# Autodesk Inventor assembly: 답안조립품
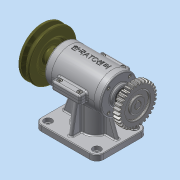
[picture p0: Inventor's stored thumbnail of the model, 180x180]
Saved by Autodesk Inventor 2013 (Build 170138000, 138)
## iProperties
Created: 2015-09
Part Number: 답안조립품
Document SubType Name: Assembly
Designer: dgall
Mass: 2246.61 g
Surface Area: 1628.2 cm^2
Volume: 528.248 cm^3
Density: 4.25295 g/cm^3
Author: dgall
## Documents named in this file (17)
- C:\Users\dgall\Desktop\350907V1040\답안조립품.iam
- C:\Users\dgall\Desktop\350907V1040\1본체.ipt
- C:\Users\dgall\Desktop\350907V1040\2본체 커버.ipt
- C:\Users\dgall\Desktop\350907V1040\3앞커버.ipt
- C:\Users\dgall\Desktop\350907V1040\4뒤커버.ipt
- C:\Users\dgall\Desktop\350907V1040\5편심축.ipt
- C:\Users\dgall\Desktop\350907V1040\6V-벨트풀리.ipt
- C:\Users\dgall\Desktop\350907V1040\7슬라이드.ipt
- C:\Users\dgall\Desktop\350907V1040\8스퍼기어.ipt
- C:\Users\dgall\Desktop\350907V1040\9베어링 6202.ipt
- C:\Users\dgall\Desktop\350907V1040\10베어링 6201.ipt
- C:\Users\dgall\Desktop\350907V1040\11오일실.ipt
- C:\Users\dgall\Desktop\350907V1040\12M4x0.5x14.ipt
- C:\Users\dgall\Desktop\350907V1040\13M3x0.5x8.ipt
- C:\Users\dgall\Desktop\350907V1040\14멈춤나사.ipt
- C:\Users\dgall\Desktop\350907V1040\15키4x4.ipt
- C:\Users\dgall\Desktop\350907V1040\16가변스프링.ipt
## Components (28 placed, 15 different names)
1. 1본체:1 — 각도:1
2. 2본체 커버:1
3. 3앞커버:1
4. 4뒤커버:1
5. 5편심축:1 — 각도:1
6. 6V-벨트풀리:1
7. 7슬라이드:1
8. 9베어링 6202:1
9. 10베어링 6201:1
10. 11오일실:1
11. 11오일실:2
12. M4x0.5x14:1
13. M4x0.5x14:2
14. M4x0.5x14:3
15. M4x0.5x14:4
16. M3x0.5x8:1
17. M3x0.5x8:2
18. M3x0.5x8:3
19. M3x0.5x8:4
20. M3x0.5x8:5
21. M3x0.5x8:6
22. M3x0.5x8:7
23. M3x0.5x8:8
24. 14멈춤나사:1
25. 14멈춤나사:2
26. 15키4x4:1
27. 15키4x4:2
28. 16가변스프링:1
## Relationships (1: Angle 1)
- 각도:1 [Angle]: 1본체:1 ↔ 5편심축:1
